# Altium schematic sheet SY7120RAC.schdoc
size 127 x 101 mm
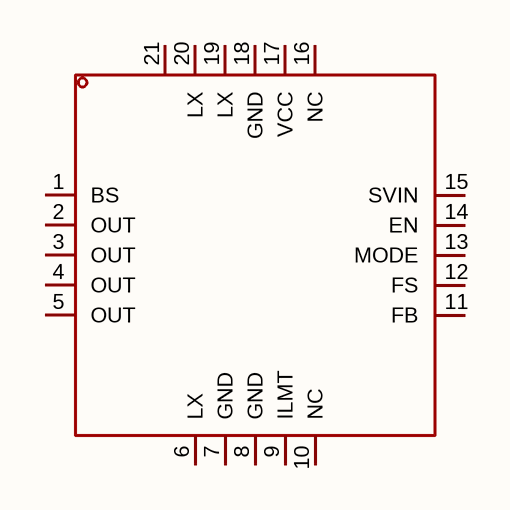
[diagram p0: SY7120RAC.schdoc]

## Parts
U?  sy7120rac  [QFN-20_L3.0-W3.0-P0.45-BL-EP1.0]  (value not drawn)

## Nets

Not connected (* = marked no-connect by the designer): U? 1(BS) 2(OUT) 3(OUT) 4(OUT) 5(OUT) 6(LX) 7(GND) 8(GND) 9(ILMT) 10(NC) 11(FB) 12(FS) 13(MODE) 14(EN) 15(SVIN) 16(NC) 17(VCC) 18(GND) 19(LX) 20(LX) 21(PAD)

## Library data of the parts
U? = sy7120rac: 功能类型:升压型;工作电压:2.8V~16V;输出电压:-;输出电流:-;输出类型:可调;; Manufacturer: Silergy(矽力杰); AddInBom: yes; ModelId: 993738199e794b9a9ab189fd78fc7651; ModelTransform: 118.8974,118.8974,0,90,0,0,0.007,-0.002,0; Function: 升压型; Frequency - Switching: 300kHz~2MHz；400kHz~600kHz; Synchronous Rectifier: 是; Number of Outputs: 1; Topology: 升压式; Quiescent Current: 200uA; Switch tube (built-in/external): 内置; Output Type: 可调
